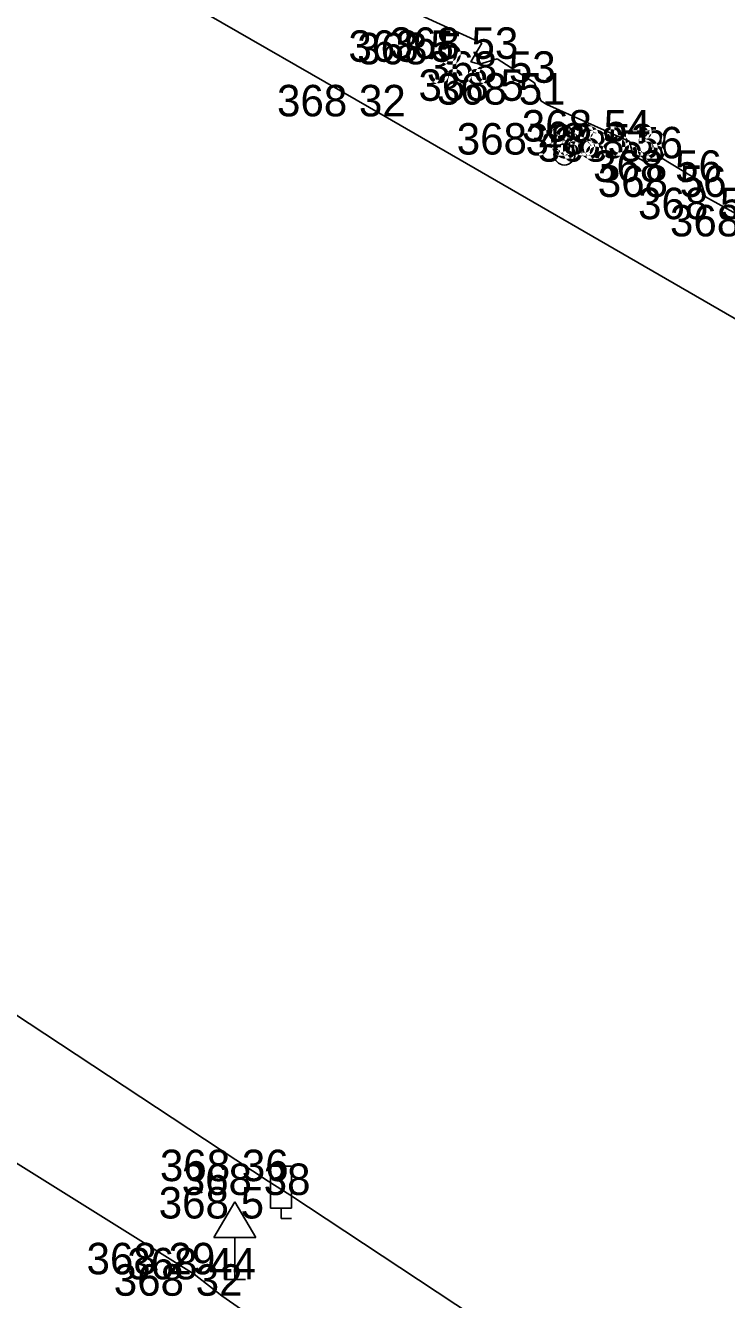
# Model space of a CAD drawing. Extents: x -688316 to -688024, y -973785 to -973591.
# Drawn here: x -688125.42 to -688108.72, y -973669.95 to -973639.59 of the extents above; entities that cross this region are included whole.
import ezdxf

# ---------------------------------------------------------------- set-up
doc = ezdxf.new("R2010")
doc.units = 0
for name, color, linetype in [('Default', 7, 'Continuous'), ('Vrstva 10', 7, 'Continuous'), ('Vrstva 3', 7, 'Continuous'), ('Vrstva 31', 7, 'Continuous'), ('Vrstva 34', 7, 'Continuous'), ('Vrstva 5', 7, 'Continuous'), ('Vrstva 58', 7, 'Continuous'), ('Vrstva 6', 7, 'Continuous')]:
    doc.layers.add(name, color=color, linetype=linetype)

# ---------------------------------------------------------------- blocks, each defined once
blk = doc.blocks.new('DZ')
at = {"layer": 'Vrstva 34'}
for p, q in [((-5, 10), (0, 18.5)), ((0, 18.5), (5, 10)), ((-5, 10), (5, 10)), ((0, 0), (0, 10)), ((-2.49, 0), (2.49, 0))]:
    blk.add_line(p, q, dxfattribs=at)
blk = doc.blocks.new('POINT_DISPLAY')
at = {"layer": 'Default'}
blk.add_line((0, 0), (0, 0), dxfattribs=at)
blk = doc.blocks.new('SKRIN')
at = {"layer": 'Vrstva 58'}
for p, q in [((-2.5, 2.5), (-2.5, 12.5)), ((-2.5, 12.5), (2.5, 12.5)), ((2.5, 12.5), (2.5, 2.5)), ((2.5, 2.5), (-2.5, 2.5)), ((-2.5, 2.5), (0, 2.5)), ((0, 2.5), (0, 0)), ((0, 0), (2.5, 0))]:
    blk.add_line(p, q, dxfattribs=at)
blk.add_blockref('POINT_DISPLAY', (2.5, 2.5), dxfattribs=at)
blk = doc.blocks.new('SP')
at = {"layer": 'Vrstva 31'}
blk.add_circle((0, 0), 2.5, dxfattribs=at)

msp = doc.modelspace()

# ---------------------------------------------------------------- linework, layer by layer
at = {"layer": 'Vrstva 10'}
for p, q in [((-688128.13, -973635.26), (-688116.85, -973641.76)), ((-688116.85, -973641.76), (-688105.92, -973648.08)), ((-688119.64, -973667.13), (-688126.24, -973662.78)), ((-688127.84, -973665.32), (-688121.4, -973669.35)), ((-688119.12, -973667.46), (-688119.64, -973667.13)), ((-688102.38, -973678.5), (-688119.12, -973667.46)), ((-688121.4, -973669.35), (-688120.74, -973669.86)), ((-688120.74, -973669.86), (-688111.87, -973676.05))]:
    msp.add_line(p, q, dxfattribs=at)
at = {"layer": 'Vrstva 5'}
for points in [[(-688127.39, -973632.92), (-688126.75, -973633.39), (-688126.83, -973633.52), (-688126.17, -973633.9), (-688125.91, -973634.05), (-688122.3, -973635.83), (-688122.45, -973636.07), (-688122.11, -973636.25), (-688121.52, -973636.59), (-688121.44, -973636.46), (-688120.76, -973636.84), (-688118.29, -973638.05), (-688118.38, -973638.25), (-688117.46, -973638.76), (-688117.34, -973639), (-688116.87, -973639.22), (-688116.45, -973639.15), (-688114.55, -973640.02), (-688114.81, -973640.46), (-688114.6, -973640.52), (-688114.18, -973640.39)], [(-688113.29, -973640.96), (-688113.14, -973641.39), (-688113, -973641.48), (-688111.03, -973642.36), (-688110.94, -973642.69), (-688110.66, -973642.84), (-688110.26, -973642.76)], [(-688109.33, -973643.32), (-688109.22, -973643.68), (-688108.26, -973644.21)]]:
    msp.add_lwpolyline(points, dxfattribs=at)
at = {"layer": 'Vrstva 6'}
for p, q in [((-688114.18, -973640.39), (-688113.29, -973640.96)), ((-688110.26, -973642.76), (-688109.33, -973643.32))]:
    msp.add_line(p, q, dxfattribs=at)

# ---------------------------------------------------------------- block references
at = {"layer": 'Vrstva 31', "xscale": 0.1, "yscale": 0.10000000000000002}
msp.add_blockref('SP', (-688112.58, -973642.67), dxfattribs=at)
at = {"layer": 'Vrstva 34', "xscale": 0.1, "yscale": 0.10000000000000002}
msp.add_blockref('DZ', (-688120.43, -973669.47), dxfattribs=at)
msp.add_blockref('DZ', (-688120.43, -973669.47), dxfattribs=at)
msp.add_blockref('DZ', (-688120.43, -973669.47), dxfattribs=at)
msp.add_blockref('DZ', (-688120.43, -973669.47), dxfattribs=at)
at = {"layer": 'Vrstva 58', "xscale": 0.1, "yscale": 0.10000000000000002}
msp.add_blockref('SKRIN', (-688119.33, -973668.02), dxfattribs=at)
msp.add_blockref('SKRIN', (-688119.33, -973668.02), dxfattribs=at)
msp.add_blockref('SKRIN', (-688119.33, -973668.02), dxfattribs=at)
msp.add_blockref('SKRIN', (-688119.33, -973668.02), dxfattribs=at)

# ---------------------------------------------------------------- texts
at = {"layer": 'Vrstva 3'}
for s, p in [('368 53 ', (-688116.746, -973640.39)), ('368 53 ', (-688116.746, -973640.39)), ('368 53 ', (-688116.746, -973640.39)), ('368 53 ', (-688116.746, -973640.39)), ('368 53 ', (-688116.746, -973640.39)), ('368 53 ', (-688116.746, -973640.39)), ('368 53 ', (-688116.746, -973640.39)), ('368 5  ', (-688117.727, -973640.46)), ('368 5  ', (-688117.727, -973640.46)), ('368 5  ', (-688117.727, -973640.46)), ('368 5  ', (-688117.727, -973640.46)), ('368 5  ', (-688117.727, -973640.46)), ('368 5  ', (-688117.727, -973640.46)), ('368 5  ', (-688117.727, -973640.46)), ('368 5  ', (-688117.517, -973640.52)), ('368 5  ', (-688117.517, -973640.52)), ('368 5  ', (-688117.517, -973640.52)), ('368 5  ', (-688117.517, -973640.52)), ('368 5  ', (-688117.517, -973640.52)), ('368 5  ', (-688117.517, -973640.52)), ('368 5  ', (-688117.517, -973640.52)), ('368 53 ', (-688115.856, -973640.96)), ('368 53 ', (-688115.856, -973640.96)), ('368 53 ', (-688115.856, -973640.96)), ('368 53 ', (-688115.856, -973640.96)), ('368 53 ', (-688115.856, -973640.96)), ('368 53 ', (-688115.856, -973640.96)), ('368 53 ', (-688115.856, -973640.96)), ('368 5  ', (-688116.057, -973641.39)), ('368 5  ', (-688116.057, -973641.39)), ('368 5  ', (-688116.057, -973641.39)), ('368 5  ', (-688116.057, -973641.39)), ('368 5  ', (-688116.057, -973641.39)), ('368 5  ', (-688116.057, -973641.39)), ('368 5  ', (-688116.057, -973641.39)), ('368 51 ', (-688115.621, -973641.48)), ('368 51 ', (-688115.621, -973641.48)), ('368 51 ', (-688115.621, -973641.48)), ('368 51 ', (-688115.621, -973641.48)), ('368 51 ', (-688115.621, -973641.48)), ('368 51 ', (-688115.621, -973641.48)), ('368 51 ', (-688115.621, -973641.48)), ('368 32 ', (-688119.428, -973641.76)), ('368 32 ', (-688119.428, -973641.76)), ('368 32 ', (-688119.428, -973641.76)), ('368 32 ', (-688119.428, -973641.76)), ('368 32 ', (-688119.428, -973641.76)), ('368 32 ', (-688119.428, -973641.76)), ('368 32 ', (-688119.428, -973641.76)), ('368 54 ', (-688113.596, -973642.36)), ('368 54 ', (-688113.596, -973642.36)), ('368 54 ', (-688113.596, -973642.36)), ('368 54 ', (-688113.596, -973642.36)), ('368 54 ', (-688113.596, -973642.36)), ('368 54 ', (-688113.596, -973642.36)), ('368 54 ', (-688113.596, -973642.36)), ('368 48 ', (-688115.146, -973642.67)), ('368 48 ', (-688115.146, -973642.67)), ('368 48 ', (-688115.146, -973642.67)), ('368 48 ', (-688115.146, -973642.67)), ('368 48 ', (-688115.146, -973642.67)), ('368 48 ', (-688115.146, -973642.67)), ('368 48 ', (-688115.146, -973642.67)), ('368 53 ', (-688113.506, -973642.69)), ('368 53 ', (-688113.506, -973642.69)), ('368 53 ', (-688113.506, -973642.69)), ('368 53 ', (-688113.506, -973642.69)), ('368 53 ', (-688113.506, -973642.69)), ('368 53 ', (-688113.506, -973642.69)), ('368 53 ', (-688113.506, -973642.69)), ('368 53 ', (-688113.226, -973642.84)), ('368 53 ', (-688113.226, -973642.84)), ('368 53 ', (-688113.226, -973642.84)), ('368 53 ', (-688113.226, -973642.84)), ('368 53 ', (-688113.226, -973642.84)), ('368 53 ', (-688113.226, -973642.84)), ('368 53 ', (-688113.226, -973642.84)), ('368 56 ', (-688112.826, -973642.76)), ('368 56 ', (-688112.826, -973642.76)), ('368 56 ', (-688112.826, -973642.76)), ('368 56 ', (-688112.826, -973642.76)), ('368 56 ', (-688112.826, -973642.76)), ('368 56 ', (-688112.826, -973642.76)), ('368 56 ', (-688112.826, -973642.76)), ('368 56 ', (-688111.896, -973643.32)), ('368 56 ', (-688111.896, -973643.32)), ('368 56 ', (-688111.896, -973643.32)), ('368 56 ', (-688111.896, -973643.32)), ('368 56 ', (-688111.896, -973643.32)), ('368 56 ', (-688111.896, -973643.32)), ('368 56 ', (-688111.896, -973643.32)), ('368 56 ', (-688111.786, -973643.68)), ('368 56 ', (-688111.786, -973643.68)), ('368 56 ', (-688111.786, -973643.68)), ('368 56 ', (-688111.786, -973643.68)), ('368 56 ', (-688111.786, -973643.68)), ('368 56 ', (-688111.786, -973643.68)), ('368 56 ', (-688111.786, -973643.68)), ('368 57 ', (-688110.826, -973644.21)), ('368 57 ', (-688110.826, -973644.21)), ('368 57 ', (-688110.826, -973644.21)), ('368 57 ', (-688110.826, -973644.21)), ('368 57 ', (-688110.826, -973644.21)), ('368 57 ', (-688110.826, -973644.21)), ('368 57 ', (-688110.826, -973644.21)), ('368 59 ', (-688110.066, -973644.62)), ('368 59 ', (-688110.066, -973644.62)), ('368 59 ', (-688110.066, -973644.62)), ('368 59 ', (-688110.066, -973644.62)), ('368 59 ', (-688110.066, -973644.62)), ('368 59 ', (-688110.066, -973644.62)), ('368 59 ', (-688110.066, -973644.62)), ('368 36 ', (-688122.218, -973667.13)), ('368 36 ', (-688122.218, -973667.13)), ('368 36 ', (-688122.218, -973667.13)), ('368 36 ', (-688122.218, -973667.13)), ('368 36 ', (-688122.218, -973667.13)), ('368 36 ', (-688122.218, -973667.13)), ('368 36 ', (-688122.218, -973667.13)), ('368 38 ', (-688121.698, -973667.46)), ('368 38 ', (-688121.698, -973667.46)), ('368 38 ', (-688121.698, -973667.46)), ('368 38 ', (-688121.698, -973667.46)), ('368 38 ', (-688121.698, -973667.46)), ('368 38 ', (-688121.698, -973667.46)), ('368 38 ', (-688121.698, -973667.46)), ('368 5  ', (-688122.247, -973668.02)), ('368 5  ', (-688122.247, -973668.02)), ('368 5  ', (-688122.247, -973668.02)), ('368 5  ', (-688122.247, -973668.02)), ('368 5  ', (-688122.247, -973668.02)), ('368 5  ', (-688122.247, -973668.02)), ('368 5  ', (-688122.247, -973668.02)), ('368 29 ', (-688123.966, -973669.35)), ('368 29 ', (-688123.966, -973669.35)), ('368 29 ', (-688123.966, -973669.35)), ('368 29 ', (-688123.966, -973669.35)), ('368 29 ', (-688123.966, -973669.35)), ('368 29 ', (-688123.966, -973669.35)), ('368 29 ', (-688123.966, -973669.35)), ('368 44 ', (-688122.996, -973669.47)), ('368 44 ', (-688122.996, -973669.47)), ('368 44 ', (-688122.996, -973669.47)), ('368 44 ', (-688122.996, -973669.47)), ('368 44 ', (-688122.996, -973669.47)), ('368 44 ', (-688122.996, -973669.47)), ('368 44 ', (-688122.996, -973669.47)), ('368 32 ', (-688123.318, -973669.86)), ('368 32 ', (-688123.318, -973669.86)), ('368 32 ', (-688123.318, -973669.86)), ('368 32 ', (-688123.318, -973669.86)), ('368 32 ', (-688123.318, -973669.86)), ('368 32 ', (-688123.318, -973669.86)), ('368 32 ', (-688123.318, -973669.86))]:
    msp.add_text(s, height=0.75, dxfattribs=at).set_placement(p)

doc.saveas('drawing.dxf')
